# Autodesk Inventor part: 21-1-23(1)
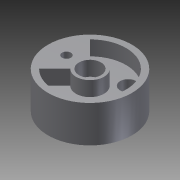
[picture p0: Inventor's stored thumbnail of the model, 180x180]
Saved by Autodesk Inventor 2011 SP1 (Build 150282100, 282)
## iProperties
Created: 2014-01
Part Number: 21-1-23(1)
Document SubType Name: Modeling
Designer: Administrator
Density: 1 g/cm^3
Author: Administrator
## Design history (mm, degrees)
sketch "草图1"
  geometry: C1 r 28.5 at (0, 0); 1 further point
  constraints: 1 centre point, 1 coincident
  dimensions: "d0" = 57 diameter of C1
extrude "拉伸1" new body sketch "草图1" distance "d1" = 25; taper "d2" = 0 deg
sketch "草图2"
  geometry: C1 r 28.5 at (0, 0) reference; 1 further point
  dimensions: "d3" = 16 distance of C1.centre point (16, 0)
hole "Hole1" sketch "草图2" at (16, 0) diameter "d4" = 6; stored, may be unused: countersink angle "d8" = 90 deg, drill point angle "d10" = 118 deg; dims "d5" = 6, "d6" = 10, "d7" = 5, "d9" = 8
hole "Hole2" diameter "d13" = 10; stored, may be unused: countersink angle "d17" = 90 deg, drill point angle "d19" = 118 deg; dims "d11" = 10, "d12" = 10, "d14" = 6, "d15" = 15, "d16" = 10, "d18" = 8
sketch "草图3"
  geometry: L1 (-6.718, -6.718)-(-17.324, -17.324); L2 (-6.718, 6.718)-(-17.324, 17.324); C1 r 28.5 at (0, 0) reference; A1 r 9.5 centre (0, 0) between (-6.718, -6.718) and (-6.718, 6.718); A2 r 24.5 centre (0, 0) between (-17.324, -17.324) and (-17.324, 17.324)
  constraints: 4 end point, 4 point on circle, 2 centre point, 2 coincident
  dimensions: "d20" = 19 diameter of A1; "d21" = 49 diameter of A2
extrude "拉伸2" cut sketch "草图3" distance "d23" = 10; taper "d24" = 0 deg
sketch "草图4"
  geometry: A1 r 9.5 centre (0, 0) between (-6.718, -6.718) and (-6.718, 6.718) reference; 1 further point
  dimensions: "d26" = 13 horizontal distance of point (13, 13) A1.centre
hole "Hole3" sketch "草图4" at (13, 13) diameter "d27" = 11; stored, may be unused: countersink angle "d31" = 90 deg, drill point angle "d33" = 118 deg; dims "d28" = 6, "d29" = 15, "d30" = 10, "d32" = 8
pattern_circular "环形阵列1" dims angle "d35" = -90 deg
node "实体1"
